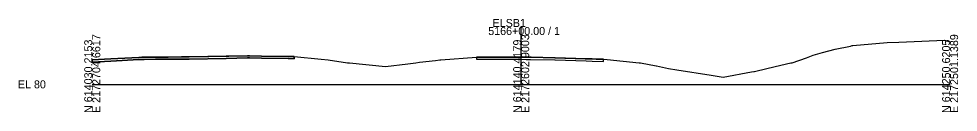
# Model space of a CAD drawing. Extents: x -26 to 1303, y -3010 to 12023.
# Drawn here: x -25.7 to 302.8, y -3009.7 to -2977.2 of the extents above; entities that cross this region are included whole.
import ezdxf

# ---------------------------------------------------------------- set-up
doc = ezdxf.new("R2010")
doc.units = 0
for name, color, linetype in [('RD_GPK_XS_Cell', 7, 'Continuous'), ('RD_XS_ExGround', 7, 'Continuous'), ('RD_XS_ExPaveRet', 7, 'Continuous')]:
    doc.layers.add(name, color=color, linetype=linetype)

msp = doc.modelspace()

# ---------------------------------------------------------------- linework, layer by layer
at = {"layer": 'RD_GPK_XS_Cell'}
for p, q in [((150, -3000), (150, -2980)), ((0, -3000), (150, -3000)), ((150, -3000), (300, -3000))]:
    msp.add_line(p, q, dxfattribs=at)
at = {"layer": 'RD_XS_ExGround'}
msp.add_lwpolyline([(0, -2991.49), (6.46, -2991.14), (17.32, -2990.55), (26.6, -2990.49), (32.17, -2990.45), (40.8, -2990.29), (54.83, -2990.05), (59.24, -2990.12), (70.58, -2990.31), (80.02, -2991.24), (82.47, -2991.5), (89.22, -2992.46), (89.5, -2992.5), (89.94, -2992.54), (102.6, -2993.79), (110.42, -2992.79), (113.19, -2992.48), (114.42, -2992.32), (119.99, -2991.68), (121.51, -2991.5), (121.96, -2991.46), (134.36, -2990.49), (146.45, -2990.49), (149.89, -2990.5), (153.47, -2990.57), (161.78, -2990.73), (172.42, -2991.07), (176.28, -2991.19), (178.78, -2991.27), (180.07, -2991.39), (191.27, -2992.49), (191.59, -2992.52), (191.72, -2992.54), (191.76, -2992.55), (197.24, -2993.5), (197.33, -2993.52), (201.51, -2994.49), (204.38, -2994.93), (216.49, -2996.78), (220.65, -2997.44), (230.58, -2995.69), (231.37, -2995.54), (231.64, -2995.5), (232.03, -2995.41), (238.8, -2993.83), (244.3, -2992.55), (244.52, -2992.5), (244.72, -2992.44), (249.73, -2990.78), (252.06, -2989.83), (253.69, -2989.37), (255.4, -2988.89), (259.83, -2987.78), (265.12, -2986.63), (265.77, -2986.5), (265.98, -2986.49), (277.98, -2985.44), (282.1, -2985.3), (290.13, -2984.97), (297.98, -2984.64), (300, -2985.21)], dxfattribs=at)
at = {"layer": 'RD_XS_ExPaveRet'}
for p, q in [((6.46, -2991.14), (0, -2991.49)), ((70.58, -2990.31), (68.49, -2990.27)), ((134.36, -2990.49), (134.36, -2990.49))]:
    msp.add_line(p, q, dxfattribs=at)
for points in [[(6.46, -2991.89), (0, -2992.24), (0, -2992.24), (0, -2991.49), (0, -2991.49), (6.46, -2991.14), (6.46, -2991.14), (16.33, -2990.6), (16.33, -2990.6), (17.32, -2990.55), (17.32, -2990.55), (18.16, -2990.54), (18.16, -2990.54), (22.13, -2990.52), (22.13, -2990.52), (30.49, -2990.46), (30.49, -2990.46), (32.17, -2990.45), (32.17, -2990.45), (33.91, -2990.42), (33.91, -2990.42), (46.88, -2990.19), (46.88, -2990.19), (54.34, -2990.06), (54.34, -2990.06), (54.83, -2990.05), (54.83, -2990.05), (54.98, -2990.05), (54.98, -2990.05), (59.24, -2990.12), (59.24, -2990.12), (68.49, -2990.27), (68.49, -2990.27), (70.58, -2990.31), (70.58, -2990.31), (70.58, -2990.75), (70.58, -2990.75), (70.58, -2991.06), (70.58, -2991.06), (68.49, -2991.02), (68.49, -2991.02), (59.24, -2990.87), (59.24, -2990.87), (54.98, -2990.8), (54.98, -2990.8), (54.83, -2990.8), (54.83, -2990.8), (54.34, -2990.81), (54.34, -2990.81), (46.88, -2990.94), (46.88, -2990.94), (33.91, -2991.17), (33.91, -2991.17), (32.17, -2991.2), (32.17, -2991.2), (30.49, -2991.21), (30.49, -2991.21), (22.13, -2991.27), (22.13, -2991.27), (18.16, -2991.29), (18.16, -2991.29), (17.32, -2991.3), (17.32, -2991.3), (16.33, -2991.35), (16.33, -2991.35), (6.46, -2991.89)], [(0, -2991.49), (0, -2992.24), (6.46, -2991.89), (16.33, -2991.35), (17.32, -2991.3), (18.16, -2991.29), (22.13, -2991.27), (30.49, -2991.21), (32.17, -2991.2), (33.91, -2991.17), (46.88, -2990.94), (54.34, -2990.81), (54.83, -2990.8), (54.98, -2990.8), (59.24, -2990.87), (68.49, -2991.02), (70.58, -2991.06), (70.58, -2990.75), (70.58, -2990.31)], [(17.32, -2990.55), (16.33, -2990.6), (6.46, -2991.14)], [(31.24, -2990.46), (26.6, -2990.49), (22.13, -2990.52), (18.16, -2990.54), (17.32, -2990.55)], [(46.86, -2990.19), (33.91, -2990.42), (32.17, -2990.45), (31.24, -2990.46)], [(54.34, -2990.06), (46.88, -2990.19), (46.86, -2990.19)], [(68.49, -2990.27), (59.24, -2990.12), (54.98, -2990.05), (54.83, -2990.05), (54.34, -2990.06)], [(178.78, -2991.27), (178.78, -2991.27), (174.84, -2991.14), (172.72, -2991.07), (161.88, -2990.73), (161.78, -2990.73), (153.31, -2990.56), (151.78, -2990.53), (149.9, -2990.5), (149.89, -2990.5), (148.08, -2990.5), (146.45, -2990.49), (134.75, -2990.49), (134.36, -2990.49), (134.36, -2990.49), (134.36, -2990.49), (134.36, -2991.14), (134.36, -2991.24), (134.36, -2991.24), (134.36, -2991.24), (134.75, -2991.24), (146.45, -2991.24), (148.08, -2991.25), (149.89, -2991.25), (149.9, -2991.25), (151.78, -2991.28), (153.31, -2991.31), (161.78, -2991.48), (161.88, -2991.48), (172.72, -2991.82), (174.84, -2991.89), (178.78, -2992.02), (178.78, -2992.02), (178.78, -2992.02), (178.78, -2991.92), (178.78, -2991.27), (178.78, -2991.27)], [(149.9, -2990.5), (149.89, -2990.5), (148.08, -2990.5), (146.45, -2990.49), (134.75, -2990.49), (134.36, -2990.49)], [(134.36, -2990.49), (134.36, -2991.14), (134.36, -2991.24), (134.36, -2991.24), (134.75, -2991.24), (146.45, -2991.24), (148.08, -2991.25), (149.89, -2991.25), (149.9, -2991.25), (151.78, -2991.28), (153.31, -2991.31), (161.78, -2991.48), (161.88, -2991.48), (172.72, -2991.82), (174.84, -2991.89), (178.78, -2992.02), (178.78, -2992.02), (178.78, -2991.92), (178.78, -2991.27), (178.78, -2991.27)], [(172.42, -2991.07), (161.78, -2990.73), (153.47, -2990.57), (153.31, -2990.56), (151.78, -2990.53), (149.9, -2990.5)], [(178.78, -2991.27), (176.28, -2991.19), (172.42, -2991.07)]]:
    msp.add_lwpolyline(points, dxfattribs=at)

# ---------------------------------------------------------------- texts
at = {"layer": 'RD_GPK_XS_Cell'}
for s, p in [('ELSB1', (140, -2980)), ('5166+00.00 / 1', (138.48, -2982.8)), ('EL 80', (-26, -3001.4))]:
    msp.add_text(s, height=2.8, dxfattribs=at).set_placement(p)
for s, p in [('E 2172704.6617', (2.8, -3010)), ('E 2172602.9003', (152.8, -3010)), ('E 2172501.1389', (302.8, -3010)), ('N 614030.2153', (0, -3010)), ('N 614140.4179', (150, -3010)), ('N 614250.6205', (300, -3010))]:
    msp.add_text(s, height=2.8, rotation=90, dxfattribs=at).set_placement(p)

doc.saveas('drawing.dxf')
